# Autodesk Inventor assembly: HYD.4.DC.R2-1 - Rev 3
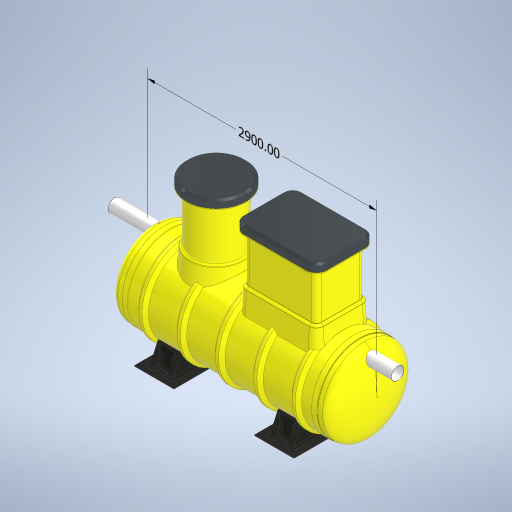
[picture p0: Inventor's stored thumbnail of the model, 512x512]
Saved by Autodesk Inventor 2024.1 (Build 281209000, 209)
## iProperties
Created: 2023-10
Part Number: HYD.4.DC.R2-1 - Rev 3
Document SubType Name: Assembly
Designer: macga
Author: macga
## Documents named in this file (43)
- D:\$ Protector Vault\Workspace\Automation Files\1. Protector Stardard Products\HydroProtectors\FAMILY\HYD.4 - Vernon\HYD.4.DC.R2-1 - Rev 3.iam
- D:\$ Protector Vault\Workspace\1. Protector Stardard Products\HydroProtectors\FAMILY\HORIZONTAL TANK - IPART\HORIZONTAL TANK - IPART.ipt
- D:\$ Protector Vault\Workspace\1. Protector Stardard Products\HydroProtectors\FAMILY\DOME - IPART\DOME - IPART.ipt
- D:\$ Protector Vault\Workspace\1. Protector Stardard Products\HydroProtectors\FAMILY\ACDTUBE - IPART\ACDTUBE - IPART.ipt
- D:\$ Protector Vault\Workspace\1. Protector Stardard Products\HydroProtectors\FAMILY\ACD FLOAT VALVE - IPART\ACD.FloatValve - IASSY\ACD.FVALVE.225.ASSY.iam
- D:\$ Protector Vault\Workspace\1. Protector Stardard Products\HydroProtectors\FAMILY\ACD FLOAT VALVE - IPART\ACD.FloatValve - IASSY.iam
- D:\$ Protector Vault\Workspace\1. Protector Stardard Products\HydroProtectors\FAMILY\SU.600Dia Manway Adaptor - IPART\SU.MWA.HS.6R - IPART.ipt
- D:\$ Protector Vault\Workspace\1. Protector Stardard Products\HydroProtectors\FAMILY\600x900mm Manway Adaptor - IPART\600x900mm Manway Adaptor - IPART.ipt
- D:\$ Protector Vault\Workspace\1. Protector Stardard Products\HydroProtectors\Coalescer Guide Rail.ipt
- D:\$ Protector Vault\Workspace\1. Protector Stardard Products\Standard Components\600mm Riser.ipt
- D:\$ Protector Vault\Workspace\1. Protector Stardard Products\Standard Components\600x900 - 600mm Manway Riser.ipt
- D:\$ Protector Vault\Workspace\1. Protector Stardard Products\Standard Components\Flanged Vent.ipt
- D:\$ Protector Vault\Workspace\1. Protector Stardard Products\HydroProtectors\Upper Guide Rai Braket.ipt
- D:\$ Protector Vault\Workspace\1. Protector Stardard Products\Xtremeprotector\Vault\Lifting Eye.ipt
- D:\$ Protector Vault\Workspace\1. Protector Stardard Products\Xtremeprotector\Vault\Chain.ipt
- D:\$ Protector Vault\Workspace\1. Protector Stardard Products\Standard Components\600mm Cast Iron Cover ST\600mm Cass D Cover-01.ipt
- D:\$ Protector Vault\Workspace\1. Protector Stardard Products\Standard Components\600mm Cast Iron Cover ST.ipt
- D:\$ Protector Vault\Workspace\Automation Files\600x900mm Manway Cover ST B and D\600x900mm Manway Cover-D.ipt
- D:\$ Protector Vault\Workspace\Automation Files\600x900mm Manway Cover ST B and D.ipt
- D:\$ Protector Vault\Workspace\1. Protector Stardard Products\HydroProtectors\FAMILY\OUTLET ELBOW - IPART\OUTLET ELBOW - IPART.ipt
- D:\$ Protector Vault\Workspace\1. Protector Stardard Products\HydroProtectors\FAMILY\INLET PIPE ELBOW- IPART\INLET PIPE ELBOW- IPART.ipt
- D:\$ Protector Vault\Workspace\1. Protector Stardard Products\HydroProtectors\HYD Oil Probe\Oil Probe Assembly.iam
- D:\$ Protector Vault\Workspace\1. Protector Stardard Products\HydroProtectors\FAMILY\FOOT - IPART\FRP Foot - IPART.ipt
- D:\$ Protector Vault\Workspace\1. Protector Stardard Products\Ecoprotectors\ISO 4065 Pipe DN160x1.3xS63 - 3000.ipt
- D:\$ Protector Vault\Workspace\1. Protector Stardard Products\HydroProtectors\FAMILY\OUTLET ELBOW - IPART\OUTLET ELBOW - IPART\OutletPipeElbow.150D-100DCoupling.ipt
- D:\$ Protector Vault\Workspace\1. Protector Stardard Products\HydroProtectors\FAMILY\INLET PIPE ELBOW- IPART\INLET PIPE ELBOW- IPART\InletPipeElbow.150D.ipt
- D:\$ Protector Vault\Workspace\1. Protector Stardard Products\HydroProtectors\FAMILY\COALESCER FILTER - IPART\CF-R2.iam
- D:\$ Protector Vault\Workspace\1. Protector Stardard Products\Horizontal Storage Tanks\ISO 4065 Pipe DN160x1.3xS63 - 1000.ipt
- D:\$ Protector Vault\Workspace\1. Protector Stardard Products\HydroProtectors\FAMILY\DOME - IPART\DOME - IPART\SU.DOME.1050-6.ipt
- D:\$ Protector Vault\Workspace\1. Protector Stardard Products\HydroProtectors\FAMILY\HYD.BAFFLE - IPART\SU.BAFFLE.1050\SU.BAFFLE.1050.ipt
- D:\$ Protector Vault\Workspace\1. Protector Stardard Products\HydroProtectors\FAMILY\HYD.BAFFLE - IPART\SU.BAFFLE.1050.ipt
- D:\$ Protector Vault\Workspace\1. Protector Stardard Products\HydroProtectors\FAMILY\ACD Base - IPART\SU.ACDBASE.1050\SU.ACDBASE.1050.ipt
- D:\$ Protector Vault\Workspace\1. Protector Stardard Products\HydroProtectors\FAMILY\ACD Base - IPART\SU.ACDBASE.1050.ipt
- D:\$ Protector Vault\Workspace\1. Protector Stardard Products\HydroProtectors\FAMILY\CF.BASE - IPART\CF BASE SINGLE - IPART\SU.CFBASE.1050\SU.CFBASE.1050.ipt
- D:\$ Protector Vault\Workspace\1. Protector Stardard Products\HydroProtectors\FAMILY\CF.BASE - IPART\CF BASE SINGLE - IPART\SU.CFBASE.1050.ipt
- D:\$ Protector Vault\Workspace\1. Protector Stardard Products\HydroProtectors\FAMILY\HORIZONTAL TANK - IPART\HORIZONTAL TANK - IPART\WIN.HB.1050x2460L-6.ipt
- D:\$ Protector Vault\Workspace\1. Protector Stardard Products\HydroProtectors\FAMILY\FOOT - IPART\FRP Foot - IPART\SU.HS.FOOT.1050.ipt
- D:\$ Protector Vault\Workspace\1. Protector Stardard Products\HydroProtectors\FAMILY\600x900mm Manway Adaptor - IPART\600x900mm Manway Adaptor - IPART\SU.MRADAPTOR.1050.600Lx900W.ipt
- D:\$ Protector Vault\Workspace\1. Protector Stardard Products\HydroProtectors\FAMILY\SU.600Dia Manway Adaptor - IPART\Horizontal 600mmDia Manway Adaptor (FLANGED) SU.MWA.HS.6R-1850-1850\SU.MWA.HS.6R-1050.ipt
- D:\$ Protector Vault\Workspace\1. Protector Stardard Products\HydroProtectors\FAMILY\ACDTUBE - IPART\ACDTUBE - IPART\ACDTUBE.225-1100.ipt
- D:\$ Protector Vault\Workspace\Automation Files\1. Protector Stardard Products\HydroProtectors\FAMILY\CF.BASE - IPART\Moulds\Coalescer Guide Rail-0122.ipt
- D:\$ Protector Vault\Workspace\1. Protector Stardard Products\Xtremeprotector\Vault\Chain\Chain-26.ipt
- D:\$ Protector Vault\Workspace\1. Protector Stardard Products\Trade Waste Sampling Point Assembly 150.iam
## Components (30 placed, 26 different names)
1. WIN.HB.1050x2460L-6:1
2. SU.DOME.1050-6:1 — Mate:3, Mate:4, Angle:7, Mate:6, Flush:59, Tangent:4
3. SU.DOME.1050-6:2 — Mate:1, Mate:5, Angle:8
4. SU.BAFFLE.1050:1 — Mate:6
5. SU.ACDBASE.1050:1 — Mate:7
6. ACDTUBE.225-1100:1 — Angle:11, Mate:11, Mate:22
7. ACD.FVALVE.225.ASSY:1 [sub-assembly] — Mate:11, Flush:2
8. SU.CFBASE.1050:1
9. SU.MWA.HS.6R-1050:1
10. SU.MRADAPTOR.1050.600Lx900W:1 — Mate:24, Mate:30, Mate:31, Mate:32, Mate:36, Mate:37
11. CF-R2:1 [sub-assembly]
12. Coalescer Guide Rail-0122:1 — Mate:38, Mate:39, Flush:23
13. 600mm Riser:1 — Flush:22, Mate:33, Mate:44, Mate:45, Flush:2
14. 600x900 - 600mm Manway Riser:1
15. Flanged Vent:1 — Mate:34, Mate:35
16. Flanged Vent:2 — Mate:36, Mate:37
17. Upper Guide Rai Braket:1 — Mate:38, Mate:39, Flush:23
18. Lifting Eye:1 — Mate:40, Mate:41, Mate:42, Tangent:3
19. Chain-26:1 — Tangent:3
20. 600mm Cass D Cover-01:1 — Mate:44, Mate:45
21. 600x900mm Manway Cover-D:1 — Mate:46, Flush:24, Flush:25
22. ISO 4065 Pipe DN160x1.3xS63 - 3000:1 — Mate:47
23. OutletPipeElbow.150D-100DCoupling:1 — Mate:51
24. InletPipeElbow.150D:1 — Mate:55, Mate:67, Mate:68
25. Oil Probe Assembly:1 [sub-assembly] — Mate:58, Flush:57, Angle:17
26. SU.HS.FOOT.1050:1 — Mate:59, Mate:60, Angle:15
27. SU.HS.FOOT.1050:2 — Mate:61, Mate:62, Angle:16
28. ISO 4065 Pipe DN160x1.3xS63 - 1000:1 — Mate:69, Mate:70
29. ISO 4065 Pipe DN160x1.3xS63 - 3000:3 — Flush:59, Mate:67, Mate:68, Tangent:4
30. Trade Waste Sampling Point Assembly 150:1 [sub-assembly] — Mate:69, Mate:70
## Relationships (52: Mate 37, Flush 7, Angle 6, Tangent 2)
- Mate:1: SU.DOME.1050-6:2
- Mate:3: SU.DOME.1050-6:1
- Mate:4: SU.DOME.1050-6:1
- Mate:5: SU.DOME.1050-6:2
- Angle:7: SU.DOME.1050-6:1
- Angle:8: SU.DOME.1050-6:2
- Mate:6: SU.DOME.1050-6:1 ↔ SU.BAFFLE.1050:1
- Mate:7: SU.ACDBASE.1050:1
- Angle:11: ACDTUBE.225-1100:1
- Mate:11: ACDTUBE.225-1100:1 ↔ ACD.FVALVE.225.ASSY:1
- Flush:2: ACD.FVALVE.225.ASSY:1 ↔ 600mm Riser:1
- Mate:22: ACDTUBE.225-1100:1
- Mate:24: SU.MRADAPTOR.1050.600Lx900W:1
- Mate:30: SU.MRADAPTOR.1050.600Lx900W:1
- Mate:31: SU.MRADAPTOR.1050.600Lx900W:1
- Mate:32: SU.MRADAPTOR.1050.600Lx900W:1
- Flush:22: 600mm Riser:1
- Mate:33: 600mm Riser:1
- Mate:34: Flanged Vent:1
- Mate:35: Flanged Vent:1
- Mate:36: SU.MRADAPTOR.1050.600Lx900W:1 ↔ Flanged Vent:2
- Mate:37: SU.MRADAPTOR.1050.600Lx900W:1 ↔ Flanged Vent:2
- Mate:38: Coalescer Guide Rail-0122:1 ↔ Upper Guide Rai Braket:1
- Mate:39: Coalescer Guide Rail-0122:1 ↔ Upper Guide Rai Braket:1
- Flush:23: Coalescer Guide Rail-0122:1 ↔ Upper Guide Rai Braket:1
- Mate:40: Lifting Eye:1
- Mate:41: Lifting Eye:1
- Mate:42: Lifting Eye:1
- Tangent:3: Lifting Eye:1 ↔ Chain-26:1
- Mate:44: 600mm Riser:1 ↔ 600mm Cass D Cover-01:1
- Mate:45: 600mm Riser:1 ↔ 600mm Cass D Cover-01:1
- Mate:46: 600x900mm Manway Cover-D:1
- Flush:24: 600x900mm Manway Cover-D:1
- Flush:25: 600x900mm Manway Cover-D:1
- Mate:47: ISO 4065 Pipe DN160x1.3xS63 - 3000:1
- Mate:51: OutletPipeElbow.150D-100DCoupling:1
- Mate:55: InletPipeElbow.150D:1
- Mate:58: Oil Probe Assembly:1
- Flush:57: Oil Probe Assembly:1
- Mate:59: SU.HS.FOOT.1050:1
- Mate:60: SU.HS.FOOT.1050:1
- Mate:61: SU.HS.FOOT.1050:2
- Mate:62: SU.HS.FOOT.1050:2
- Angle:15: SU.HS.FOOT.1050:1
- Angle:16: SU.HS.FOOT.1050:2
- Angle:17: Oil Probe Assembly:1
- Flush:59: SU.DOME.1050-6:1 ↔ ISO 4065 Pipe DN160x1.3xS63 - 3000:3
- Mate:67: InletPipeElbow.150D:1 ↔ ISO 4065 Pipe DN160x1.3xS63 - 3000:3
- Mate:68: InletPipeElbow.150D:1 ↔ ISO 4065 Pipe DN160x1.3xS63 - 3000:3
- Tangent:4: SU.DOME.1050-6:1 ↔ ISO 4065 Pipe DN160x1.3xS63 - 3000:3
- Mate:69: ISO 4065 Pipe DN160x1.3xS63 - 1000:1 ↔ Trade Waste Sampling Point Assembly 150:1
- Mate:70: ISO 4065 Pipe DN160x1.3xS63 - 1000:1 ↔ Trade Waste Sampling Point Assembly 150:1
